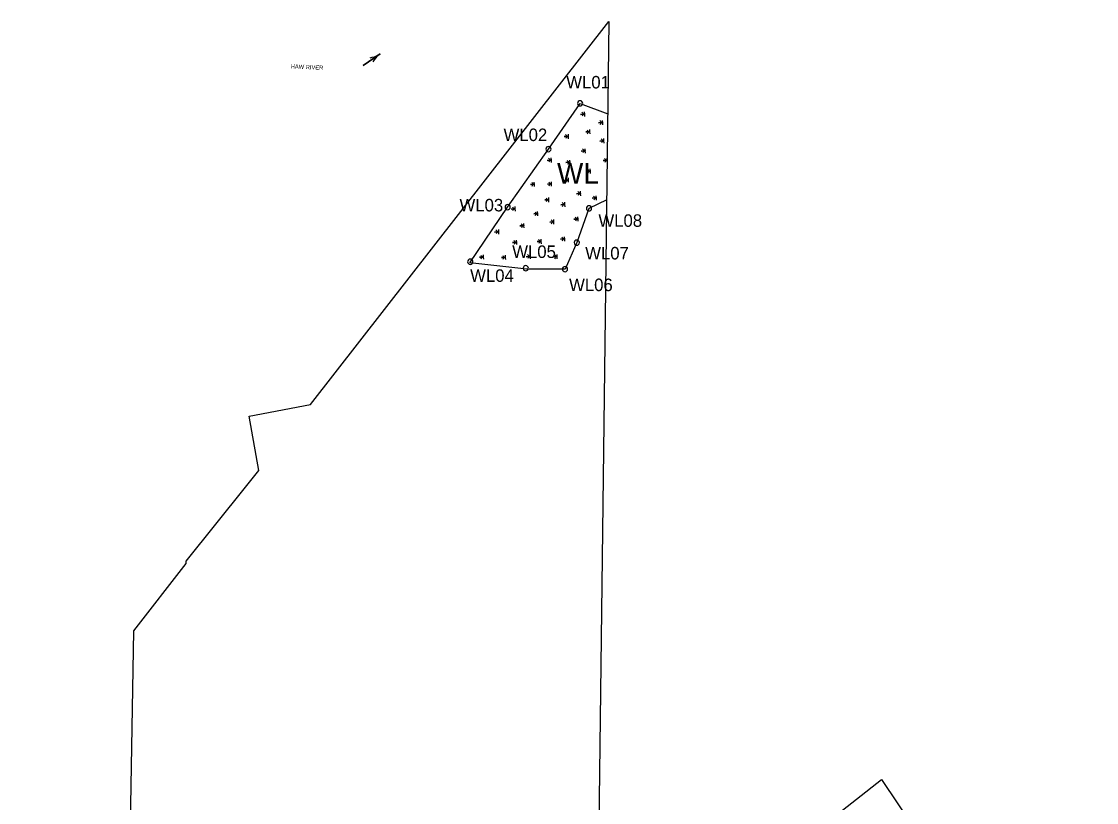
# Model space of a CAD drawing. Extents: x 1807340 to 1808565, y 913462 to 916154.
# Drawn here: x 1807430 to 1808463, y 915405 to 916154 of the extents above; entities that cross this region are included whole.
import ezdxf

# ---------------------------------------------------------------- set-up
doc = ezdxf.new("R2010")
doc.units = 0
for name, color, linetype in [('Default', 7, 'Continuous'), ('Exist Environmental Wetland Boundary', 7, 'Continuous'), ('Exist Hydro River Flow Arrow CELL', 7, 'Continuous'), ('Exist Hydro Stream or Body of Water Text', 7, 'Continuous'), ('Old_Level_60', 7, 'Continuous'), ('Prop PHM Study Limits Alternate 1', 7, 'Continuous')]:
    doc.layers.add(name, color=color, linetype=linetype)

# ---------------------------------------------------------------- blocks, each defined once
blk = doc.blocks.new('WetlandPoint')
at = {"layer": 'Default'}
for start, end in [(0, 180), (180, 0)]:
    blk.add_arc((0, 0), 0.782, start, end, dxfattribs=at)

msp = doc.modelspace()

# ---------------------------------------------------------------- linework, layer by layer
at = {"layer": 'Exist Environmental Wetland Boundary'}
for points in [[(1807992.2, 915983.4), (1807975.1, 915975.1), (1807963.4, 915942.2), (1807952.1, 915916.8), (1807915.4, 915916.8), (1807860.8, 915922.7), (1807897, 915976.3), (1807936.2, 916032), (1807966.6, 916075.9), (1807993.2, 916065.7)], [(1807971.2, 916063.4), (1807971, 916065.6), (1807967.1, 916065.3), (1807971, 916065.6), (1807970.9, 916067.7)], [(1807988.4, 916055.3), (1807988.3, 916057.5), (1807984.4, 916057.3), (1807988.3, 916057.5), (1807988.2, 916059.6)], [(1807955.5, 916042), (1807955.4, 916044.2), (1807951.4, 916044), (1807955.4, 916044.2), (1807955.3, 916046.3)], [(1807976.1, 916046.5), (1807976, 916048.7), (1807972, 916048.5), (1807976, 916048.7), (1807975.8, 916050.8)], [(1807989.6, 916037.8), (1807989.5, 916039.9), (1807985.6, 916039.7), (1807989.5, 916039.9), (1807989.4, 916042.1)], [(1807971.7, 916028.2), (1807971.6, 916030.3), (1807967.7, 916030.1), (1807971.6, 916030.3), (1807971.5, 916032.4)], [(1807939.1, 916019.2), (1807939, 916021.3), (1807935, 916021.1), (1807939, 916021.3), (1807938.9, 916023.5)], [(1807957, 916017.1), (1807956.9, 916019.3), (1807953, 916019.1), (1807956.9, 916019.3), (1807956.8, 916021.4)], [(1807992.8, 916019), (1807992.7, 916021.1), (1807988.7, 916020.9), (1807992.7, 916021.1), (1807992.5, 916023.3)], [(1807955.6, 916000.1), (1807955.5, 916002.2), (1807951.5, 916002), (1807955.5, 916002.2), (1807955.3, 916004.4)], [(1807976.6, 916008.7), (1807976.5, 916010.9), (1807972.6, 916010.6), (1807976.5, 916010.9), (1807976.4, 916013)], [(1807922.9, 915996.1), (1807922.8, 915998.3), (1807918.8, 915998.1), (1807922.8, 915998.3), (1807922.6, 916000.4)], [(1807939.2, 915996.4), (1807939.1, 915998.6), (1807935.2, 915998.4), (1807939.1, 915998.6), (1807939, 916000.7)], [(1807936.6, 915981.2), (1807936.5, 915983.4), (1807932.6, 915983.2), (1807936.5, 915983.4), (1807936.4, 915985.5)], [(1807967.2, 915987.3), (1807967.1, 915989.4), (1807963.2, 915989.2), (1807967.1, 915989.4), (1807967, 915991.6)], [(1807982.4, 915982.9), (1807982.3, 915985.1), (1807978.3, 915984.9), (1807982.3, 915985.1), (1807982.1, 915987.2)], [(1807904.4, 915972.5), (1807904.2, 915974.6), (1807900.3, 915974.4), (1807904.2, 915974.6), (1807904.1, 915976.8)], [(1807952.2, 915976.7), (1807952, 915978.8), (1807948.1, 915978.6), (1807952, 915978.8), (1807951.9, 915981)], [(1807926.1, 915967.9), (1807925.9, 915970.1), (1807922, 915969.9), (1807925.9, 915970.1), (1807925.8, 915972.2)], [(1807941.5, 915960), (1807941.4, 915962.1), (1807937.5, 915961.9), (1807941.4, 915962.1), (1807941.3, 915964.3)], [(1807964.7, 915962.7), (1807964.6, 915964.8), (1807960.6, 915964.6), (1807964.6, 915964.8), (1807964.4, 915967)], [(1807888.6, 915950.5), (1807888.5, 915952.7), (1807884.5, 915952.4), (1807888.5, 915952.7), (1807888.4, 915954.8)], [(1807912.9, 915956.4), (1807912.7, 915958.5), (1807908.8, 915958.3), (1807912.7, 915958.5), (1807912.6, 915960.7)], [(1807905.9, 915940.3), (1807905.8, 915942.4), (1807901.8, 915942.2), (1807905.8, 915942.4), (1807905.6, 915944.5)], [(1807929.4, 915941.2), (1807929.3, 915943.4), (1807925.4, 915943.2), (1807929.3, 915943.4), (1807929.2, 915945.5)], [(1807952, 915943.6), (1807951.8, 915945.8), (1807947.9, 915945.5), (1807951.8, 915945.8), (1807951.7, 915947.9)], [(1807874, 915926.3), (1807873.8, 915928.4), (1807869.9, 915928.2), (1807873.8, 915928.4), (1807873.7, 915930.6)], [(1807895.1, 915925.9), (1807895, 915928.1), (1807891, 915927.9), (1807895, 915928.1), (1807894.8, 915930.2)], [(1807918.9, 915926.8), (1807918.8, 915928.9), (1807914.9, 915928.7), (1807918.8, 915928.9), (1807918.7, 915931.1)], [(1807944.7, 915926.7), (1807944.6, 915928.8), (1807940.7, 915928.6), (1807944.6, 915928.8), (1807944.5, 915931)]]:
    msp.add_lwpolyline(points, dxfattribs=at)
for centre, radius, start, end in [((1807972.3, 916070.2), 4.81, 215.2622, 254.757), ((1807971.4, 916062.5), 3.07, 97.2751, 160.6697), ((1807989.6, 916062.1), 4.81, 215.2622, 254.757), ((1807988.7, 916054.4), 3.07, 97.2751, 160.6697), ((1807956.6, 916048.8), 4.81, 215.2622, 254.757), ((1807977.2, 916053.3), 4.81, 215.2622, 254.757), ((1807976.4, 916045.6), 3.07, 97.2751, 160.6697), ((1807955.8, 916041.1), 3.07, 97.2751, 160.6697), ((1807990.8, 916044.6), 4.81, 215.2622, 254.757), ((1807989.9, 916036.9), 3.07, 97.2751, 160.6697), ((1807972.9, 916034.9), 4.81, 215.2622, 254.757), ((1807972, 916027.3), 3.07, 97.2751, 160.6697), ((1807940.3, 916026), 4.81, 215.2622, 254.757), ((1807939.4, 916018.3), 3.07, 97.2751, 160.6697), ((1807958.2, 916023.9), 4.81, 215.2622, 254.757), ((1807957.3, 916016.2), 3.07, 97.2751, 160.6697), ((1807993.9, 916025.7), 4.81, 215.2622, 254.757), ((1807993.1, 916018.1), 3.07, 97.2751, 160.6697), ((1807956.7, 916006.9), 4.81, 215.2622, 254.757), ((1807977.8, 916015.5), 4.81, 215.2622, 254.757), ((1807976.9, 916007.8), 3.07, 97.2751, 160.6697), ((1807924, 916002.9), 4.81, 215.2622, 254.757), ((1807923.1, 915995.2), 3.07, 97.2751, 160.6697), ((1807940.4, 916003.2), 4.81, 215.2622, 254.757), ((1807939.5, 915995.5), 3.07, 97.2751, 160.6697), ((1807955.9, 915999.2), 3.07, 97.2751, 160.6697), ((1807937.8, 915988), 4.81, 215.2622, 254.757), ((1807936.9, 915980.3), 3.07, 97.2751, 160.6697), ((1807968.4, 915994.1), 4.81, 215.2622, 254.757), ((1807967.5, 915986.4), 3.07, 97.2751, 160.6697), ((1807983.5, 915989.7), 4.81, 215.2622, 254.757), ((1807982.6, 915982), 3.07, 97.2751, 160.6697), ((1807905.5, 915979.3), 4.81, 215.2622, 254.757), ((1807904.6, 915971.6), 3.07, 97.2751, 160.6697), ((1807953.3, 915983.5), 4.81, 215.2622, 254.757), ((1807952.4, 915975.8), 3.07, 97.2751, 160.6697), ((1807927.2, 915974.7), 4.81, 215.2622, 254.757), ((1807926.3, 915967), 3.07, 97.2751, 160.6697), ((1807942.7, 915966.8), 4.81, 215.2622, 254.757), ((1807965.8, 915969.5), 4.81, 215.2622, 254.757), ((1807965, 915961.8), 3.07, 97.2751, 160.6697), ((1807889.7, 915957.3), 4.81, 215.2622, 254.757), ((1807888.9, 915949.6), 3.07, 97.2751, 160.6697), ((1807914, 915963.1), 4.81, 215.2622, 254.757), ((1807913.1, 915955.5), 3.07, 97.2751, 160.6697), ((1807941.8, 915959.1), 3.07, 97.2751, 160.6697), ((1807907, 915947), 4.81, 215.2622, 254.757), ((1807906.1, 915939.4), 3.07, 97.2751, 160.6697), ((1807930.6, 915948), 4.81, 215.2622, 254.757), ((1807929.7, 915940.3), 3.07, 97.2751, 160.6697), ((1807953.1, 915950.4), 4.81, 215.2622, 254.757), ((1807952.2, 915942.7), 3.07, 97.2751, 160.6697), ((1807875.1, 915933.1), 4.81, 215.2622, 254.757), ((1807874.2, 915925.4), 3.07, 97.2751, 160.6697), ((1807896.2, 915932.7), 4.81, 215.2622, 254.757), ((1807895.3, 915925), 3.07, 97.2751, 160.6697), ((1807920.1, 915933.5), 4.81, 215.2622, 254.757), ((1807919.2, 915925.9), 3.07, 97.2751, 160.6697), ((1807945.9, 915933.5), 4.81, 215.2622, 254.757), ((1807945, 915925.8), 3.07, 97.2751, 160.6697)]:
    msp.add_arc(centre, radius, start, end, dxfattribs=at)
at = {"layer": 'Exist Hydro River Flow Arrow CELL'}
msp.add_line((1807766.3, 916117.8), (1807766.3, 916117.8), dxfattribs=at)
msp.add_lwpolyline([(1807765, 916119.7), (1807767, 916120.1), (1807769, 916120.7), (1807771, 916121.5), (1807772.8, 916122.4), (1807774.6, 916123.5), (1807758.1, 916112.1), (1807774.6, 916123.5), (1807772.9, 916122.3), (1807771.4, 916120.9), (1807770, 916119.3), (1807768.7, 916117.7), (1807767.6, 916115.9)], dxfattribs=at)
at = {"layer": 'Prop PHM Study Limits Alternate 1'}
msp.add_lwpolyline([(1807430.1, 914388.9), (1807519.9, 914687), (1807522.8, 914696.1), (1807538, 915569.7), (1807588.4, 915634.3), (1807588.3, 915636.5), (1807645.3, 915707.7), (1807658.1, 915723.7), (1807648.7, 915775.6), (1807707.5, 915787), (1807994.3, 916154.4), (1807983.4, 915279.5), (1808055, 915268.9), (1808255.9, 915426.9), (1808462.5, 915119.6), (1807995.2, 914569.7)], dxfattribs=at)

# ---------------------------------------------------------------- block references
at = {"layer": 'Old_Level_60', "xscale": 3.198862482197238, "yscale": 3.198862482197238}
for p in [(1807966.6, 916075.9), (1807936.2, 916032), (1807897, 915976.3), (1807975.1, 915975.1), (1807963.4, 915942.2), (1807861.1, 915923.9), (1807914.4, 915917.7), (1807952.1, 915916.8)]:
    msp.add_blockref('WetlandPoint', p, dxfattribs=at)

# ---------------------------------------------------------------- texts
at = {"layer": 'Exist Hydro Stream or Body of Water Text'}
msp.add_text('HAW RIVER', height=4, rotation=357.4251, dxfattribs=at).set_placement((1807688.6, 916109.5))
at = {"layer": 'Old_Level_60'}
for s, height, p in [('WL01', 12, (1807953.3, 916090.2)), ('WL02', 12, (1807893.1, 916039.7)), ('WL', 20, (1807944.4, 915998.7)), ('WL03', 12, (1807850.8, 915972.2)), ('WL08', 12, (1807984.2, 915957.4)), ('WL05', 12, (1807901.4, 915927.5)), ('WL07', 12, (1807971.5, 915926.1)), ('WL04', 12, (1807861, 915904.6)), ('WL06', 12, (1807956, 915895.7))]:
    msp.add_text(s, height=height, dxfattribs=at).set_placement(p)

doc.saveas('drawing.dxf')
